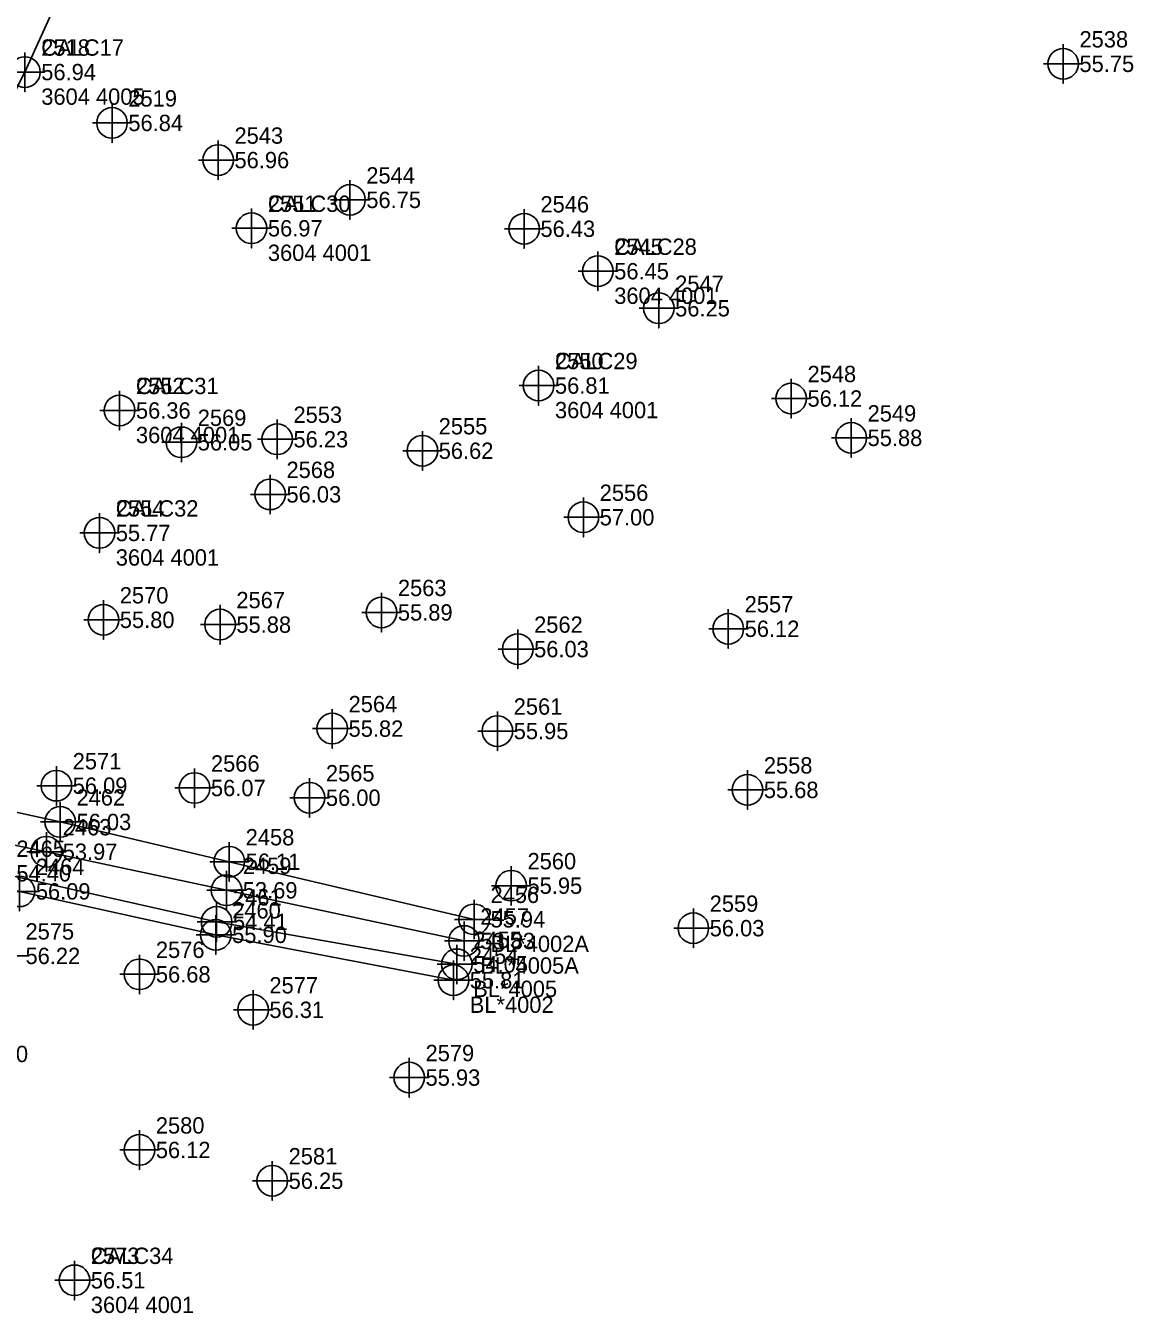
# Model space of a CAD drawing. Extents: x 2062781 to 2066835, y 358981 to 366501.
# Drawn here: x 2066219.6 to 2066388.9, y 365322.6 to 365519.6 of the extents above; entities that cross this region are included whole.
import ezdxf

# ---------------------------------------------------------------- set-up
doc = ezdxf.new("R2010")
doc.units = 0
for name, color, linetype in [('Exist DTM Breakline', 7, 'Continuous'), ('Exist DTM Breakline Cogo Comment', 7, 'Continuous'), ('Exist DTM Breakline Cogo Elevation', 7, 'Continuous'), ('Exist DTM Breakline Cogo Number', 7, 'Continuous'), ('Exist DTM Breakline Cogo Point CELL', 7, 'Continuous'), ('Exist DTM Regular Point CELL', 7, 'Continuous'), ('Exist DTM Regular Point Cogo Elevation', 7, 'Continuous'), ('Exist DTM Regular Point Cogo Number', 7, 'Continuous'), ('Exist DTM Ridgeline', 7, 'Continuous'), ('Exist DTM Ridgeline Cogo Comment', 7, 'Continuous'), ('Exist DTM Ridgeline Cogo Elevation', 7, 'Continuous'), ('Exist DTM Ridgeline Cogo Number', 7, 'Continuous'), ('Exist DTM Ridgeline Cogo Point CELL', 7, 'Continuous'), ('Exist Vegetation Woods Line Cogo Comment', 7, 'Continuous'), ('Exist Vegetation Woods Line Cogo Elevation', 7, 'Continuous'), ('Exist Vegetation Woods Line Cogo Number', 7, 'Continuous'), ('Exist Vegetation Woods Line Cogo Point CELL', 7, 'Continuous')]:
    doc.layers.add(name, color=color, linetype=linetype)

msp = doc.modelspace()

# ---------------------------------------------------------------- linework, layer by layer
at = {"layer": 'Exist DTM Breakline'}
for points in [[(2066170.96, 365418.99), (2066195.94, 365466.06), (2066219.45, 365512.47), (2066243.69, 365565.98), (2066276.1, 365619.15), (2066302.66, 365675.9), (2066323.83, 365725.38)], [(2066222.73, 365393.22), (2066201.01, 365397.72), (2066199.46, 365396.09), (2066200.48, 365393.93), (2066215.64, 365389.93)], [(2066286.6, 365379.57), (2066250.27, 365387.32), (2066222.73, 365393.22)], [(2066285.51, 365376), (2066248.77, 365382.49), (2066215.64, 365389.93)]]:
    msp.add_lwpolyline(points, dxfattribs=at)
at = {"layer": 'Exist DTM Breakline Cogo Point CELL'}
for points in [[(2066219.45, 365515.47), (2066219.45, 365509.47), (2066219.45, 365512.47), (2066222.45, 365512.47), (2066216.45, 365512.47)], [(2066222.73, 365396.22), (2066222.73, 365390.22), (2066222.73, 365393.22), (2066225.73, 365393.22), (2066219.73, 365393.22)], [(2066250.27, 365390.32), (2066250.27, 365384.32), (2066250.27, 365387.32), (2066253.27, 365387.32), (2066247.27, 365387.32)], [(2066248.77, 365385.49), (2066248.77, 365379.49), (2066248.77, 365382.49), (2066251.77, 365382.49), (2066245.77, 365382.49)], [(2066286.6, 365382.57), (2066286.6, 365376.57), (2066286.6, 365379.57), (2066289.6, 365379.57), (2066283.6, 365379.57)], [(2066285.51, 365379), (2066285.51, 365373), (2066285.51, 365376), (2066288.51, 365376), (2066282.51, 365376)]]:
    msp.add_lwpolyline(points, dxfattribs=at)
for centre in [(2066219.45, 365512.47), (2066222.73, 365393.22), (2066250.27, 365387.32), (2066248.77, 365382.49), (2066286.6, 365379.57), (2066285.51, 365376)]:
    msp.add_circle(centre, 2.34, dxfattribs=at)
at = {"layer": 'Exist DTM Regular Point CELL'}
for points in [[(2066378.22, 365516.73), (2066378.22, 365510.73), (2066378.22, 365513.73), (2066381.22, 365513.73), (2066375.22, 365513.73)], [(2066232.77, 365507.69), (2066232.77, 365501.69), (2066232.77, 365504.69), (2066235.77, 365504.69), (2066229.77, 365504.69)], [(2066249, 365502.01), (2066249, 365496.01), (2066249, 365499.01), (2066252, 365499.01), (2066246, 365499.01)], [(2066269.16, 365495.92), (2066269.16, 365489.92), (2066269.16, 365492.92), (2066272.16, 365492.92), (2066266.16, 365492.92)], [(2066254.11, 365491.58), (2066254.11, 365485.58), (2066254.11, 365488.58), (2066257.11, 365488.58), (2066251.11, 365488.58)], [(2066295.79, 365491.5), (2066295.79, 365485.5), (2066295.79, 365488.5), (2066298.79, 365488.5), (2066292.79, 365488.5)], [(2066307.07, 365485.01), (2066307.07, 365479.01), (2066307.07, 365482.01), (2066310.07, 365482.01), (2066304.07, 365482.01)], [(2066316.39, 365479.34), (2066316.39, 365473.34), (2066316.39, 365476.34), (2066319.39, 365476.34), (2066313.39, 365476.34)], [(2066298.01, 365467.52), (2066298.01, 365461.52), (2066298.01, 365464.52), (2066301.01, 365464.52), (2066295.01, 365464.52)], [(2066336.63, 365465.54), (2066336.63, 365459.54), (2066336.63, 365462.54), (2066339.63, 365462.54), (2066333.63, 365462.54)], [(2066233.93, 365463.71), (2066233.93, 365457.71), (2066233.93, 365460.71), (2066236.93, 365460.71), (2066230.93, 365460.71)], [(2066243.38, 365458.84), (2066243.38, 365452.84), (2066243.38, 365455.84), (2066246.38, 365455.84), (2066240.38, 365455.84)], [(2066258.02, 365459.31), (2066258.02, 365453.31), (2066258.02, 365456.31), (2066261.02, 365456.31), (2066255.02, 365456.31)], [(2066345.82, 365459.52), (2066345.82, 365453.52), (2066345.82, 365456.52), (2066348.82, 365456.52), (2066342.82, 365456.52)], [(2066280.23, 365457.55), (2066280.23, 365451.55), (2066280.23, 365454.55), (2066283.23, 365454.55), (2066277.23, 365454.55)], [(2066256.95, 365450.88), (2066256.95, 365444.88), (2066256.95, 365447.88), (2066259.95, 365447.88), (2066253.95, 365447.88)], [(2066304.85, 365447.38), (2066304.85, 365441.38), (2066304.85, 365444.38), (2066307.85, 365444.38), (2066301.85, 365444.38)], [(2066230.85, 365444.98), (2066230.85, 365438.98), (2066230.85, 365441.98), (2066233.85, 365441.98), (2066227.85, 365441.98)], [(2066273.99, 365432.82), (2066273.99, 365426.82), (2066273.99, 365429.82), (2066276.99, 365429.82), (2066270.99, 365429.82)], [(2066231.46, 365431.69), (2066231.46, 365425.69), (2066231.46, 365428.69), (2066234.46, 365428.69), (2066228.46, 365428.69)], [(2066249.29, 365430.96), (2066249.29, 365424.96), (2066249.29, 365427.96), (2066252.29, 365427.96), (2066246.29, 365427.96)], [(2066327.02, 365430.32), (2066327.02, 365424.32), (2066327.02, 365427.32), (2066330.02, 365427.32), (2066324.02, 365427.32)], [(2066294.82, 365427.21), (2066294.82, 365421.21), (2066294.82, 365424.21), (2066297.82, 365424.21), (2066291.82, 365424.21)], [(2066266.45, 365415.05), (2066266.45, 365409.05), (2066266.45, 365412.05), (2066269.45, 365412.05), (2066263.45, 365412.05)], [(2066291.7, 365414.68), (2066291.7, 365408.68), (2066291.7, 365411.68), (2066294.7, 365411.68), (2066288.7, 365411.68)], [(2066224.26, 365406.32), (2066224.26, 365400.32), (2066224.26, 365403.32), (2066227.26, 365403.32), (2066221.26, 365403.32)], [(2066245.4, 365405.97), (2066245.4, 365399.97), (2066245.4, 365402.97), (2066248.4, 365402.97), (2066242.4, 365402.97)], [(2066329.95, 365405.68), (2066329.95, 365399.68), (2066329.95, 365402.68), (2066332.95, 365402.68), (2066326.95, 365402.68)], [(2066262.98, 365404.48), (2066262.98, 365398.48), (2066262.98, 365401.48), (2066265.98, 365401.48), (2066259.98, 365401.48)], [(2066293.81, 365391.03), (2066293.81, 365385.03), (2066293.81, 365388.03), (2066296.81, 365388.03), (2066290.81, 365388.03)], [(2066321.67, 365384.53), (2066321.67, 365378.53), (2066321.67, 365381.53), (2066324.67, 365381.53), (2066318.67, 365381.53)], [(2066217.04, 365380.29), (2066217.04, 365374.29), (2066217.04, 365377.29), (2066220.04, 365377.29), (2066214.04, 365377.29)], [(2066236.98, 365377.47), (2066236.98, 365371.47), (2066236.98, 365374.47), (2066239.98, 365374.47), (2066233.98, 365374.47)], [(2066254.34, 365372.04), (2066254.34, 365366.04), (2066254.34, 365369.04), (2066257.34, 365369.04), (2066251.34, 365369.04)], [(2066278.22, 365361.68), (2066278.22, 365355.68), (2066278.22, 365358.68), (2066281.22, 365358.68), (2066275.22, 365358.68)], [(2066236.97, 365350.61), (2066236.97, 365344.61), (2066236.97, 365347.61), (2066239.97, 365347.61), (2066233.97, 365347.61)], [(2066257.28, 365345.9), (2066257.28, 365339.9), (2066257.28, 365342.9), (2066260.28, 365342.9), (2066254.28, 365342.9)], [(2066227.03, 365330.67), (2066227.03, 365324.67), (2066227.03, 365327.67), (2066230.03, 365327.67), (2066224.03, 365327.67)]]:
    msp.add_lwpolyline(points, dxfattribs=at)
for centre in [(2066378.22, 365513.73), (2066232.77, 365504.69), (2066249, 365499.01), (2066269.16, 365492.92), (2066254.11, 365488.58), (2066295.79, 365488.5), (2066307.07, 365482.01), (2066316.39, 365476.34), (2066298.01, 365464.52), (2066336.63, 365462.54), (2066233.93, 365460.71), (2066243.38, 365455.84), (2066258.02, 365456.31), (2066345.82, 365456.52), (2066280.23, 365454.55), (2066256.95, 365447.88), (2066304.85, 365444.38), (2066230.85, 365441.98), (2066231.46, 365428.69), (2066273.99, 365429.82), (2066249.29, 365427.96), (2066327.02, 365427.32), (2066294.82, 365424.21), (2066266.45, 365412.05), (2066291.7, 365411.68), (2066224.26, 365403.32), (2066245.4, 365402.97), (2066329.95, 365402.68), (2066262.98, 365401.48), (2066293.81, 365388.03), (2066321.67, 365381.53), (2066236.98, 365374.47), (2066254.34, 365369.04), (2066278.22, 365358.68), (2066236.97, 365347.61), (2066257.28, 365342.9), (2066227.03, 365327.67)]:
    msp.add_circle(centre, 2.34, dxfattribs=at)
at = {"layer": 'Exist DTM Ridgeline'}
for points in [[(2066218.62, 365387.16), (2066199.32, 365391.77), (2066192.18, 365396.08), (2066195.4, 365402.27), (2066201.94, 365402.8), (2066224.84, 365397.78)], [(2066288.15, 365382.88), (2066250.71, 365391.69), (2066224.84, 365397.78)], [(2066284.98, 365373.57), (2066248.64, 365380.51), (2066218.62, 365387.16)]]:
    msp.add_lwpolyline(points, dxfattribs=at)
at = {"layer": 'Exist DTM Ridgeline Cogo Point CELL'}
for points in [[(2066224.84, 365400.78), (2066224.84, 365394.78), (2066224.84, 365397.78), (2066227.84, 365397.78), (2066221.84, 365397.78)], [(2066250.71, 365394.69), (2066250.71, 365388.69), (2066250.71, 365391.69), (2066253.71, 365391.69), (2066247.71, 365391.69)], [(2066218.62, 365390.16), (2066218.62, 365384.16), (2066218.62, 365387.16), (2066221.62, 365387.16), (2066215.62, 365387.16)], [(2066288.15, 365385.88), (2066288.15, 365379.88), (2066288.15, 365382.88), (2066291.15, 365382.88), (2066285.15, 365382.88)], [(2066248.64, 365383.51), (2066248.64, 365377.51), (2066248.64, 365380.51), (2066251.64, 365380.51), (2066245.64, 365380.51)], [(2066284.98, 365376.57), (2066284.98, 365370.57), (2066284.98, 365373.57), (2066287.98, 365373.57), (2066281.98, 365373.57)]]:
    msp.add_lwpolyline(points, dxfattribs=at)
for centre in [(2066224.84, 365397.78), (2066250.71, 365391.69), (2066218.62, 365387.16), (2066288.15, 365382.88), (2066248.64, 365380.51), (2066284.98, 365373.57)]:
    msp.add_circle(centre, 2.34, dxfattribs=at)
at = {"layer": 'Exist Vegetation Woods Line Cogo Point CELL'}
for points in [[(2066219.45, 365515.47), (2066219.45, 365509.47), (2066219.45, 365512.47), (2066222.45, 365512.47), (2066216.45, 365512.47)], [(2066254.11, 365491.58), (2066254.11, 365485.58), (2066254.11, 365488.58), (2066257.11, 365488.58), (2066251.11, 365488.58)], [(2066307.07, 365485.01), (2066307.07, 365479.01), (2066307.07, 365482.01), (2066310.07, 365482.01), (2066304.07, 365482.01)], [(2066298.01, 365467.52), (2066298.01, 365461.52), (2066298.01, 365464.52), (2066301.01, 365464.52), (2066295.01, 365464.52)], [(2066233.93, 365463.71), (2066233.93, 365457.71), (2066233.93, 365460.71), (2066236.93, 365460.71), (2066230.93, 365460.71)], [(2066230.85, 365444.98), (2066230.85, 365438.98), (2066230.85, 365441.98), (2066233.85, 365441.98), (2066227.85, 365441.98)], [(2066227.03, 365330.67), (2066227.03, 365324.67), (2066227.03, 365327.67), (2066230.03, 365327.67), (2066224.03, 365327.67)]]:
    msp.add_lwpolyline(points, dxfattribs=at)
for centre in [(2066219.45, 365512.47), (2066254.11, 365488.58), (2066307.07, 365482.01), (2066298.01, 365464.52), (2066233.93, 365460.71), (2066230.85, 365441.98), (2066227.03, 365327.67)]:
    msp.add_circle(centre, 2.34, dxfattribs=at)

# ---------------------------------------------------------------- texts
at = {"layer": 'Exist DTM Breakline Cogo Comment'}
for s, p in [('BL*4005A', (2066289.1, 365374.57)), ('BL*4005', (2066288.01, 365371))]:
    msp.add_text(s, height=2.5, dxfattribs=at).set_placement(p)
at = {"layer": 'Exist DTM Breakline Cogo Elevation'}
for s, p in [('56.94', (2066221.95, 365511.22)), ('53.97', (2066225.23, 365391.97)), ('54.40', (2066218.14, 365388.68)), ('53.69', (2066252.77, 365386.07)), ('54.41', (2066251.27, 365381.24)), ('53.83', (2066289.1, 365378.32)), ('54.05', (2066288.01, 365374.75))]:
    msp.add_text(s, height=2.5, dxfattribs=at).set_placement(p)
at = {"layer": 'Exist DTM Breakline Cogo Number'}
for s, p in [('CALC17', (2066221.95, 365514.97)), ('2463', (2066225.23, 365395.72)), ('2465', (2066218.14, 365392.43)), ('2459', (2066252.77, 365389.82)), ('2461', (2066251.27, 365384.99)), ('2457', (2066289.1, 365382.07)), ('2455', (2066288.01, 365378.5))]:
    msp.add_text(s, height=2.5, dxfattribs=at).set_placement(p)
at = {"layer": 'Exist DTM Regular Point Cogo Elevation'}
for s, p in [('55.75', (2066380.72, 365512.48)), ('56.84', (2066235.27, 365503.44)), ('56.96', (2066251.5, 365497.76)), ('56.75', (2066271.66, 365491.67)), ('56.97', (2066256.61, 365487.33)), ('56.43', (2066298.29, 365487.25)), ('56.45', (2066309.57, 365480.76)), ('56.25', (2066318.89, 365475.09)), ('56.81', (2066300.51, 365463.27)), ('56.12', (2066339.13, 365461.29)), ('56.36', (2066236.43, 365459.46)), ('56.05', (2066245.88, 365454.59)), ('56.23', (2066260.52, 365455.06)), ('55.88', (2066348.32, 365455.27)), ('56.62', (2066282.73, 365453.3)), ('56.03', (2066259.45, 365446.63)), ('57.00', (2066307.35, 365443.13)), ('55.77', (2066233.35, 365440.73)), ('55.89', (2066276.49, 365428.57)), ('55.80', (2066233.96, 365427.44)), ('55.88', (2066251.79, 365426.71)), ('56.12', (2066329.52, 365426.07)), ('56.03', (2066297.32, 365422.96)), ('55.82', (2066268.95, 365410.8)), ('55.95', (2066294.2, 365410.43)), ('56.09', (2066226.76, 365402.07)), ('56.07', (2066247.9, 365401.72)), ('55.68', (2066332.45, 365401.43)), ('56.00', (2066265.48, 365400.23)), ('55.95', (2066296.31, 365386.78)), ('56.03', (2066324.17, 365380.28)), ('56.22', (2066219.54, 365376.04)), ('56.68', (2066239.48, 365373.22)), ('56.31', (2066256.84, 365367.79)), ('56.70', (2066211.57, 365361.04)), ('55.93', (2066280.72, 365357.43)), ('56.12', (2066239.47, 365346.36)), ('56.25', (2066259.78, 365341.65)), ('56.51', (2066229.53, 365326.42))]:
    msp.add_text(s, height=2.5, dxfattribs=at).set_placement(p)
at = {"layer": 'Exist DTM Regular Point Cogo Number'}
for s, p in [('2538', (2066380.72, 365516.23)), ('2519', (2066235.27, 365507.19)), ('2543', (2066251.5, 365501.51)), ('2544', (2066271.66, 365495.42)), ('CALC30', (2066256.61, 365491.08)), ('2546', (2066298.29, 365491)), ('CALC28', (2066309.57, 365484.51)), ('2547', (2066318.89, 365478.84)), ('CALC29', (2066300.51, 365467.02)), ('2548', (2066339.13, 365465.04)), ('CALC31', (2066236.43, 365463.21)), ('2569', (2066245.88, 365458.34)), ('2553', (2066260.52, 365458.81)), ('2549', (2066348.32, 365459.02)), ('2555', (2066282.73, 365457.05)), ('2568', (2066259.45, 365450.38)), ('2556', (2066307.35, 365446.88)), ('CALC32', (2066233.35, 365444.48)), ('2563', (2066276.49, 365432.32)), ('2570', (2066233.96, 365431.19)), ('2567', (2066251.79, 365430.46)), ('2557', (2066329.52, 365429.82)), ('2562', (2066297.32, 365426.71)), ('2564', (2066268.95, 365414.55)), ('2561', (2066294.2, 365414.18)), ('2571', (2066226.76, 365405.82)), ('2566', (2066247.9, 365405.47)), ('2558', (2066332.45, 365405.18)), ('2565', (2066265.48, 365403.98)), ('2560', (2066296.31, 365390.53)), ('2559', (2066324.17, 365384.03)), ('2575', (2066219.54, 365379.79)), ('2576', (2066239.48, 365376.97)), ('2577', (2066256.84, 365371.54)), ('2579', (2066280.72, 365361.18)), ('2580', (2066239.47, 365350.11)), ('2581', (2066259.78, 365345.4)), ('CALC34', (2066229.53, 365330.17))]:
    msp.add_text(s, height=2.5, dxfattribs=at).set_placement(p)
at = {"layer": 'Exist DTM Ridgeline Cogo Comment'}
for s, p in [('BL*4002A', (2066290.65, 365377.88)), ('BL*4002', (2066287.48, 365368.57))]:
    msp.add_text(s, height=2.5, dxfattribs=at).set_placement(p)
at = {"layer": 'Exist DTM Ridgeline Cogo Elevation'}
for s, p in [('56.03', (2066227.34, 365396.53)), ('56.11', (2066253.21, 365390.44)), ('56.09', (2066221.12, 365385.91)), ('55.94', (2066290.65, 365381.63)), ('55.90', (2066251.14, 365379.26)), ('55.81', (2066287.48, 365372.32))]:
    msp.add_text(s, height=2.5, dxfattribs=at).set_placement(p)
at = {"layer": 'Exist DTM Ridgeline Cogo Number'}
for s, p in [('2462', (2066227.34, 365400.28)), ('2458', (2066253.21, 365394.19)), ('2464', (2066221.12, 365389.66)), ('2456', (2066290.65, 365385.38)), ('2460', (2066251.14, 365383.01)), ('2454', (2066287.48, 365376.07))]:
    msp.add_text(s, height=2.5, dxfattribs=at).set_placement(p)
at = {"layer": 'Exist Vegetation Woods Line Cogo Comment'}
for s, p in [('3604 4005', (2066221.95, 365507.47)), ('3604 4001', (2066256.61, 365483.58)), ('3604 4001', (2066309.57, 365477.01)), ('3604 4001', (2066300.51, 365459.52)), ('3604 4001', (2066236.43, 365455.71)), ('3604 4001', (2066233.35, 365436.98)), ('3604 4001', (2066229.53, 365322.67))]:
    msp.add_text(s, height=2.5, dxfattribs=at).set_placement(p)
at = {"layer": 'Exist Vegetation Woods Line Cogo Elevation'}
for s, p in [('56.94', (2066221.95, 365511.22)), ('56.97', (2066256.61, 365487.33)), ('56.45', (2066309.57, 365480.76)), ('56.81', (2066300.51, 365463.27)), ('56.36', (2066236.43, 365459.46)), ('55.77', (2066233.35, 365440.73)), ('56.51', (2066229.53, 365326.42))]:
    msp.add_text(s, height=2.5, dxfattribs=at).set_placement(p)
at = {"layer": 'Exist Vegetation Woods Line Cogo Number'}
for s, p in [('2518', (2066221.95, 365514.97)), ('2551', (2066256.61, 365491.08)), ('2545', (2066309.57, 365484.51)), ('2550', (2066300.51, 365467.02)), ('2552', (2066236.43, 365463.21)), ('2554', (2066233.35, 365444.48)), ('2573', (2066229.53, 365330.17))]:
    msp.add_text(s, height=2.5, dxfattribs=at).set_placement(p)

doc.saveas('drawing.dxf')
